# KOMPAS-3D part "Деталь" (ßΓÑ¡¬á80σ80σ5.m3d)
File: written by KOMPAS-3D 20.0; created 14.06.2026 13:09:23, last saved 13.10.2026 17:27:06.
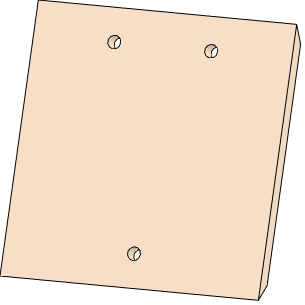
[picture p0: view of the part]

Document properties: Полное имя файла: D:\myProjects\Progect_esp32\box_compas\корпус\стенка80х80х5.m3d

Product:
- Part/product: Деталь
    Материал: Фанера, сосна,ФСФ ВВ/С  ГОСТ 3916.2-2018 (density 500 kg/m3)
    Масса: 0.0139089

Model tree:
1. Эскиз:3
2. Элемент выдавливания:4
     Расстояние 1 = 5
3. Эскиз:4  (with: Элемент выдавливания:4)
4. Элемент выдавливания:5
     Расстояние 2 = 80
5. Эскиз:5  (with: Элемент выдавливания:4)
6. Элемент выдавливания:6
     Расстояние 2 = 80
7. Эскиз:6  (with: Элемент выдавливания:4, Элемент выдавливания:6)
8. Элемент выдавливания:7  (labels: Фанера, сосна,ФСФ ВВ/С  ГОСТ 3916.2-2018)
     Расстояние 2 = 5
